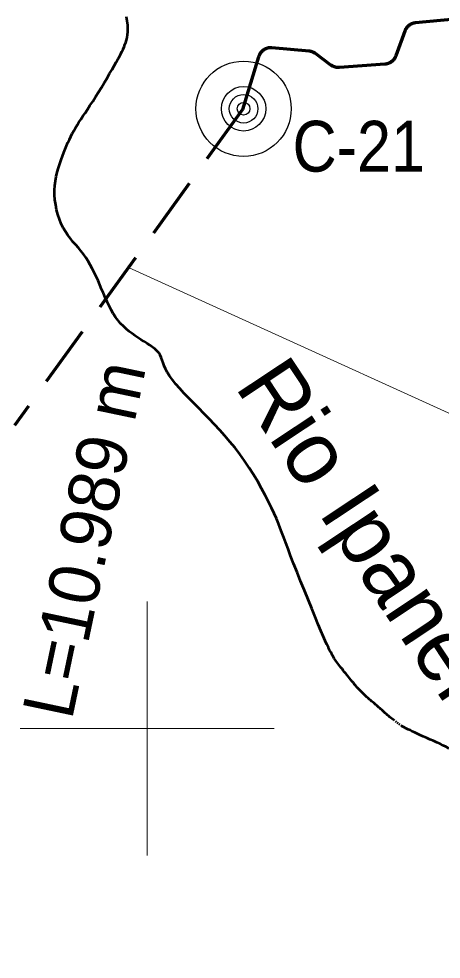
# Model space of a CAD drawing. Extents: x -1643653 to 4543381, y 1624270 to 13878484.
# Drawn here: x 698988 to 702315, y 8948185 to 8955585 of the extents above; entities that cross this region are included whole.
import ezdxf
from ezdxf.enums import TextEntityAlignment as Align

# ---------------------------------------------------------------- set-up
doc = ezdxf.new("R2010")
doc.units = 0
doc.header["$LTSCALE"] = 160
doc.linetypes.add('MEDIUM_DASHED', pattern=[4.5, 3, -1.5])
for name, color, linetype, lineweight in [('15', 7, 'Continuous', 25), ('2', 7, 'Continuous', 13), ('24', 7, 'Continuous', 25), ('50', 7, 'Continuous', 13), ('60', 7, 'Continuous', 13), ('61', 7, 'Continuous', 70)]:
    doc.layers.add(name, color=color, linetype=linetype, lineweight=lineweight)
doc.layers.add('49', color=7, linetype='Continuous')

msp = doc.modelspace()

# ---------------------------------------------------------------- linework, layer by layer
at = {"layer": '15'}
for radius in [375, 175, 112.5, 50]:
    msp.add_circle((700758.3, 8954877.2), radius, dxfattribs=at)
at = {"layer": '2'}
for p, q in [((700000, 8949000), (700000, 8951000)), ((699000, 8950000), (701000, 8950000))]:
    msp.add_line(p, q, dxfattribs=at)
at = {"layer": '24', "lineweight": 53}
for p, q in [((701961.4, 8950050), (701954.2, 8950055.7)), ((701974.9, 8950039.7), (701968.2, 8950044.7)), ((701989, 8950029.7), (701981.8, 8950034.7))]:
    msp.add_line(p, q, dxfattribs=at)
for points in [[(699780.5, 8955289.2), (699791.1, 8955309.7), (699800.6, 8955328.8), (699809.3, 8955347), (699817.2, 8955364.7), (699824.6, 8955382.1), (699831.3, 8955399.8), (699837.2, 8955418.2), (699841.9, 8955437.6), (699845.4, 8955458.6), (699847.4, 8955481.6), (699847.7, 8955507), (699846.2, 8955535.2), (699842.7, 8955566.6), (699837.2, 8955600.3)], [(699278.7, 8954120.9), (699273.4, 8954159.9), (699270.6, 8954198.8), (699270.2, 8954237.1), (699272.4, 8954274.3), (699276.9, 8954310.4), (699283.3, 8954345.4), (699291.3, 8954379.3), (699300.5, 8954412.1), (699310.6, 8954443.7), (699321.3, 8954474.3), (699332.1, 8954503.7), (699342.9, 8954532), (699353.6, 8954559.3), (699364.3, 8954585.6), (699375.2, 8954611), (699386.3, 8954635.6), (699397.6, 8954659.4), (699409.3, 8954682.5), (699421.5, 8954704.9), (699434.3, 8954726.9), (699447.7, 8954748.7), (699461.9, 8954770.9), (699477, 8954793.8), (699493.1, 8954818), (699510.4, 8954843.8), (699528.9, 8954871.7), (699548.8, 8954902.1), (699570.1, 8954935.3), (699592.4, 8954970.7), (699615.3, 8955007.6), (699638.3, 8955045.1), (699661.1, 8955082.6), (699683, 8955119.1), (699703.8, 8955154), (699722.8, 8955186.5), (699739.9, 8955216), (699755.1, 8955242.7), (699768.5, 8955267), (699780.5, 8955289.2)], [(699976.1, 8953045.1), (699952.3, 8953059.7), (699928.3, 8953074.9), (699904.2, 8953090.9), (699880.4, 8953107.7), (699857, 8953125.7), (699834.1, 8953144.9), (699811.8, 8953165.5), (699790.4, 8953187.8), (699769.9, 8953211.7), (699750.6, 8953237.6), (699732.5, 8953265.5), (699715.5, 8953295.1), (699699.4, 8953326.2), (699684.1, 8953358.4), (699669.3, 8953391.4), (699654.9, 8953424.8), (699640.7, 8953458.5), (699626.5, 8953491.9), (699612.2, 8953524.9), (699597.7, 8953557.3), (699582.7, 8953589), (699567.2, 8953619.9), (699551.1, 8953649.9), (699534.2, 8953678.8), (699516.5, 8953706.6), (699497.7, 8953733.1), (699477.8, 8953758.4), (699457.2, 8953782.8), (699436.2, 8953806.9), (699415.1, 8953831.2), (699394.3, 8953856.1), (699374.3, 8953882.2), (699355.3, 8953910.1), (699337.8, 8953940.1), (699322, 8953972.8), (699308, 8954007.6), (699296.1, 8954044.2), (699286.3, 8954082.2), (699278.7, 8954120.9)], [(701016.4, 8951651.8), (700998.5, 8951692.1), (700977.8, 8951736.6), (700954.4, 8951784.7), (700928.4, 8951835.6), (700900.1, 8951888.6), (700869.6, 8951943), (700837.1, 8951997.8), (700802.8, 8952052.4), (700766.9, 8952105.9), (700729.6, 8952157.8), (700691, 8952207.9), (700651.4, 8952256.4), (700611, 8952303.5), (700570.1, 8952349.2), (700528.7, 8952393.8), (700487.3, 8952437.2), (700445.8, 8952479.6), (700404.8, 8952521.2), (700364.6, 8952561.8), (700325.9, 8952601.2), (700289.2, 8952639.2), (700255.2, 8952675.8), (700224.5, 8952710.6), (700197.6, 8952743.6), (700175.2, 8952774.6), (700157.5, 8952803.5), (700143.9, 8952830.2), (700133.3, 8952855.1), (700124.7, 8952878.2), (700117, 8952899.6), (700109.4, 8952919.6), (700100.7, 8952938.1), (700089.9, 8952955.5), (700076.3, 8952971.8), (700060.1, 8952987.2), (700041.5, 8953002.1), (700021.1, 8953016.5), (699999.1, 8953030.8), (699976.1, 8953045.1)], [(701583.5, 8950407.2), (701573.5, 8950419.6), (701563.5, 8950432.1), (701553.6, 8950444.4), (701543.7, 8950456.7), (701534.2, 8950468.7), (701524.9, 8950480.3), (701516.1, 8950491.5), (701507.8, 8950502.2), (701500.1, 8950512.3), (701492.9, 8950522), (701486, 8950531.6), (701479.4, 8950541.3), (701472.8, 8950551.4), (701466.1, 8950562.2), (701459.3, 8950573.8), (701452.1, 8950586.6), (701444.4, 8950600.9), (701435.8, 8950617.5), (701426.1, 8950637.4), (701414.8, 8950661.5), (701401.5, 8950690.8), (701385.9, 8950726.3), (701367.7, 8950768.7), (701346.4, 8950819.2), (701321.9, 8950878.1), (701294.9, 8950943.8), (701266.2, 8951014.1), (701236.8, 8951086.9), (701207.5, 8951160.1), (701179.1, 8951231.5), (701152.6, 8951298.9), (701128.9, 8951360.2), (701108.5, 8951413.9), (701090.9, 8951461), (701075.3, 8951502.9), (701060.9, 8951541.4), (701046.8, 8951578), (701032.2, 8951614.2), (701016.4, 8951651.8)], [(701946.4, 8950061.9), (701938.1, 8950068.5), (701929.4, 8950075.4), (701920.4, 8950082.7), (701911.2, 8950090.2), (701901.9, 8950097.8), (701892.6, 8950105.7), (701883.4, 8950113.5), (701874.3, 8950121.4), (701865.5, 8950129.2), (701856.9, 8950137), (701848.4, 8950144.6), (701840.2, 8950152.2), (701832, 8950159.5), (701824.1, 8950166.6), (701816.3, 8950173.5), (701808.6, 8950180.1), (701800.9, 8950186.6), (701793.2, 8950193.1), (701785.4, 8950199.6), (701777.3, 8950206.3), (701768.9, 8950213.4), (701760, 8950220.9), (701750.6, 8950229), (701740.7, 8950237.8), (701730.2, 8950247.2), (701719.3, 8950257.2), (701708.2, 8950267.6), (701697, 8950278.3), (701685.8, 8950289.4), (701674.6, 8950300.8), (701663.7, 8950312.2), (701653.1, 8950323.8), (701642.8, 8950335.4), (701632.7, 8950347.1), (701622.8, 8950358.9), (701612.9, 8950370.8), (701603.2, 8950382.8), (701593.4, 8950395), (701583.5, 8950407.2)], [(702375.5, 8949843.3), (702354.4, 8949854.7), (702331.2, 8949866.5), (702306.2, 8949878.5), (702280.1, 8949890.7), (702253.3, 8949902.8), (702226.3, 8949914.8), (702199.6, 8949926.5), (702173.8, 8949937.8), (702149.4, 8949948.6), (702126.7, 8949958.8), (702105.9, 8949968.3), (702086.8, 8949977.3), (702069.4, 8949985.7), (702053.6, 8949993.5), (702039.4, 8950000.7), (702026.7, 8950007.4), (702015.5, 8950013.6), (702005.6, 8950019.3), (701996.8, 8950024.7)]]:
    msp.add_lwpolyline(points, dxfattribs=at)
at = {"layer": '50'}
msp.add_lwpolyline([(699852.5, 8953627.8), (703523.4, 8951959.5), (706219.7, 8951959.5)], dxfattribs=at)
at = {"layer": '60', "lineweight": 25}
msp.add_spline([(814781, 9009175.5), (814787.2, 9009173.4), (814796.9, 9009173.4), (814799.4, 9009172.4), (814805.1, 9009174.5), (814805.6, 9009176.5), (814811.7, 9009179.5), (814811.7, 9009179.5), (814801.5, 9009181), (814790.7, 9009181.5), (814784.1, 9009183.1), (814777.4, 9009185.1), (814778.4, 9009175.5)], degree=3, dxfattribs=at)
at = {"layer": '61', "linetype": 'MEDIUM_DASHED'}
msp.add_line((700750.8, 8954871.7), (698954.1, 8952383.9), dxfattribs=at)
at = {"layer": '61'}
for points in [[(702423, 8955583.1), (702111.4, 8955553), (702108.6, 8955552.7), (702105.8, 8955552.3), (702103, 8955551.8), (702100.2, 8955551.2), (702097.5, 8955550.6), (702094.8, 8955549.9), (702092, 8955549.1), (702089.3, 8955548.3), (702086.7, 8955547.3), (702084, 8955546.3), (702081.4, 8955545.2), (702078.8, 8955544.1), (702076.3, 8955542.8), (702073.8, 8955541.6), (702071.3, 8955540.2), (702068.9, 8955538.7), (702066.5, 8955537.2), (702064.1, 8955535.6), (702061.8, 8955534), (702059.6, 8955532.3), (702057.4, 8955530.5), (702055.2, 8955528.7), (702053.1, 8955526.8), (702051.1, 8955524.8), (702049.1, 8955522.8), (702047.1, 8955520.8), (702045.3, 8955518.7), (702043.5, 8955516.5), (702041.7, 8955514.3), (702040, 8955512), (702038.4, 8955509.7), (702036.8, 8955507.3), (702035.3, 8955504.9), (702033.9, 8955502.5), (702032.6, 8955500), (702031.3, 8955497.5), (702030.1, 8955494.9), (702028.9, 8955492.3), (702027.9, 8955489.7), (702027, 8955487.5), (701956.8, 8955293.4), (701955.8, 8955290.8), (701954.7, 8955288.2), (701953.6, 8955285.6), (701952.4, 8955283), (701951.1, 8955280.5), (701949.7, 8955278), (701948.3, 8955275.6), (701946.8, 8955273.2), (701945.2, 8955270.8), (701943.6, 8955268.5), (701941.9, 8955266.3), (701940.1, 8955264.1), (701938.3, 8955261.9), (701936.4, 8955259.8), (701934.5, 8955257.7), (701932.5, 8955255.7), (701930.4, 8955253.8), (701928.3, 8955251.9), (701926.1, 8955250.1), (701923.9, 8955248.3), (701921.7, 8955246.6), (701919.4, 8955245), (701917, 8955243.4), (701914.6, 8955241.9), (701912.2, 8955240.5), (701909.7, 8955239.1), (701907.2, 8955237.8), (701904.6, 8955236.6), (701902, 8955235.5), (701899.4, 8955234.4), (701896.8, 8955233.4), (701894.1, 8955232.5), (701891.4, 8955231.6), (701888.7, 8955230.9), (701885.9, 8955230.2), (701883.2, 8955229.6), (701880.4, 8955229), (701877.6, 8955228.6), (701874.8, 8955228.2), (701872, 8955227.9)], [(701872, 8955227.9), (701870, 8955227.7), (701512.9, 8955202), (701510.1, 8955201.8), (701507.2, 8955201.7), (701504.4, 8955201.7), (701501.6, 8955201.8), (701498.8, 8955201.9), (701495.9, 8955202.2), (701493.1, 8955202.5), (701490.3, 8955202.9), (701487.5, 8955203.3), (701484.8, 8955203.9), (701482, 8955204.5), (701479.3, 8955205.2), (701476.6, 8955206), (701473.9, 8955206.9), (701471.2, 8955207.8), (701468.6, 8955208.8), (701465.9, 8955209.9), (701463.4, 8955211.1), (701460.8, 8955212.3), (701458.3, 8955213.6), (701455.8, 8955215), (701453.4, 8955216.5), (701451, 8955218), (701448.7, 8955219.6), (701446.4, 8955221.2), (701446.1, 8955221.4), (701324.5, 8955311.6), (701322.2, 8955313.3), (701319.8, 8955314.9), (701317.5, 8955316.4), (701315, 8955317.8), (701312.6, 8955319.2), (701310.1, 8955320.5), (701307.5, 8955321.8), (701304.9, 8955322.9), (701302.3, 8955324), (701299.7, 8955325.1), (701297, 8955326), (701294.3, 8955326.9), (701291.6, 8955327.7), (701288.9, 8955328.4), (701286.1, 8955329), (701283.4, 8955329.6), (701280.6, 8955330.1), (701277.8, 8955330.5), (701275, 8955330.8), (701273.8, 8955330.9), (700981.4, 8955357), (700978.5, 8955357.2), (700975.7, 8955357.4), (700972.9, 8955357.4), (700970.1, 8955357.4), (700967.2, 8955357.3), (700964.4, 8955357.1), (700961.6, 8955356.8), (700958.8, 8955356.5), (700956, 8955356.1), (700953.2, 8955355.6), (700950.4, 8955355), (700947.7, 8955354.3), (700945, 8955353.6), (700942.2, 8955352.8), (700939.6, 8955351.9), (700936.9, 8955350.9), (700934.3, 8955349.9), (700931.7, 8955348.7), (700929.1, 8955347.6), (700926.6, 8955346.3), (700924.1, 8955345), (700921.6, 8955343.6), (700919.2, 8955342.1), (700916.8, 8955340.5), (700914.5, 8955338.9), (700912.2, 8955337.3), (700910, 8955335.5), (700907.8, 8955333.7), (700905.7, 8955331.9), (700903.6, 8955330), (700901.6, 8955328), (700899.6, 8955326), (700897.7, 8955323.9), (700895.9, 8955321.7), (700894.1, 8955319.5), (700892.3, 8955317.3), (700890.7, 8955315), (700889.1, 8955312.7), (700887.6, 8955310.3), (700886.1, 8955307.9), (700884.7, 8955305.4), (700883.4, 8955302.9), (700882.1, 8955300.4), (700881, 8955297.8), (700879.9, 8955295.2), (700878.8, 8955292.6), (700877.9, 8955289.9), (700877, 8955287.2), (700876.8, 8955286.5), (700750.8, 8954871.7)]]:
    msp.add_lwpolyline(points, dxfattribs=at)

# ---------------------------------------------------------------- texts
at = {"layer": '15', "width": 0.9}
msp.add_text('C-21', height=400, dxfattribs=at).set_placement((701143.7, 8954382.5))
at = {"layer": '49'}
msp.add_text('Rio Ipanema', height=500, rotation=303.53, dxfattribs=at).set_placement((701731.3, 8951111.3), align=Align.CENTER)
at = {"layer": '50'}
msp.add_text('L=10.989 m', height=400, rotation=78.119, dxfattribs=at).set_placement((699405.9, 8950059.2))

doc.saveas('drawing.dxf')
